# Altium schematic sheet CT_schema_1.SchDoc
size 550 x 503 mm
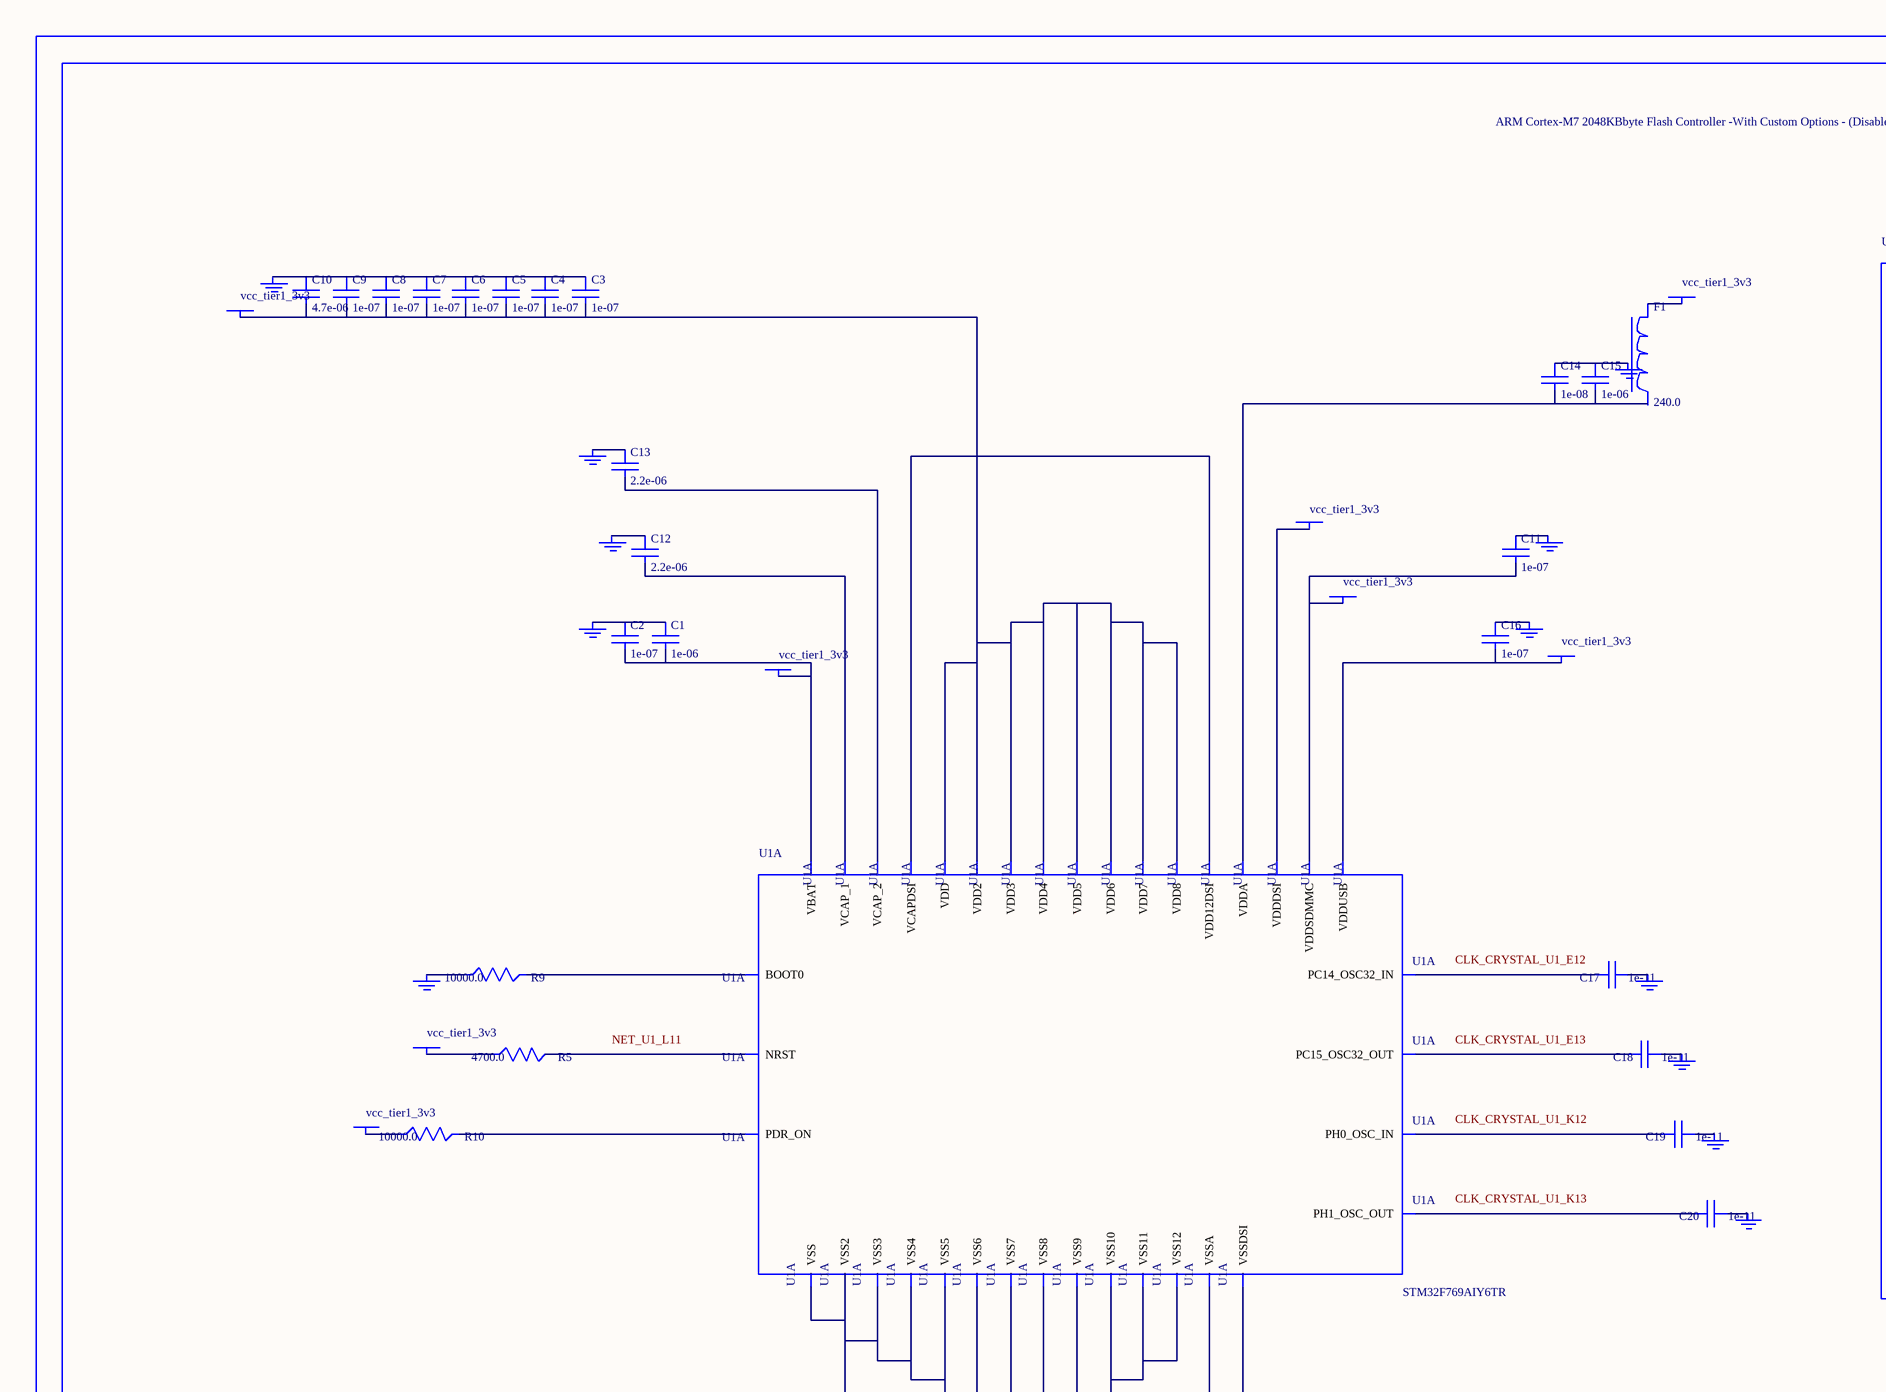
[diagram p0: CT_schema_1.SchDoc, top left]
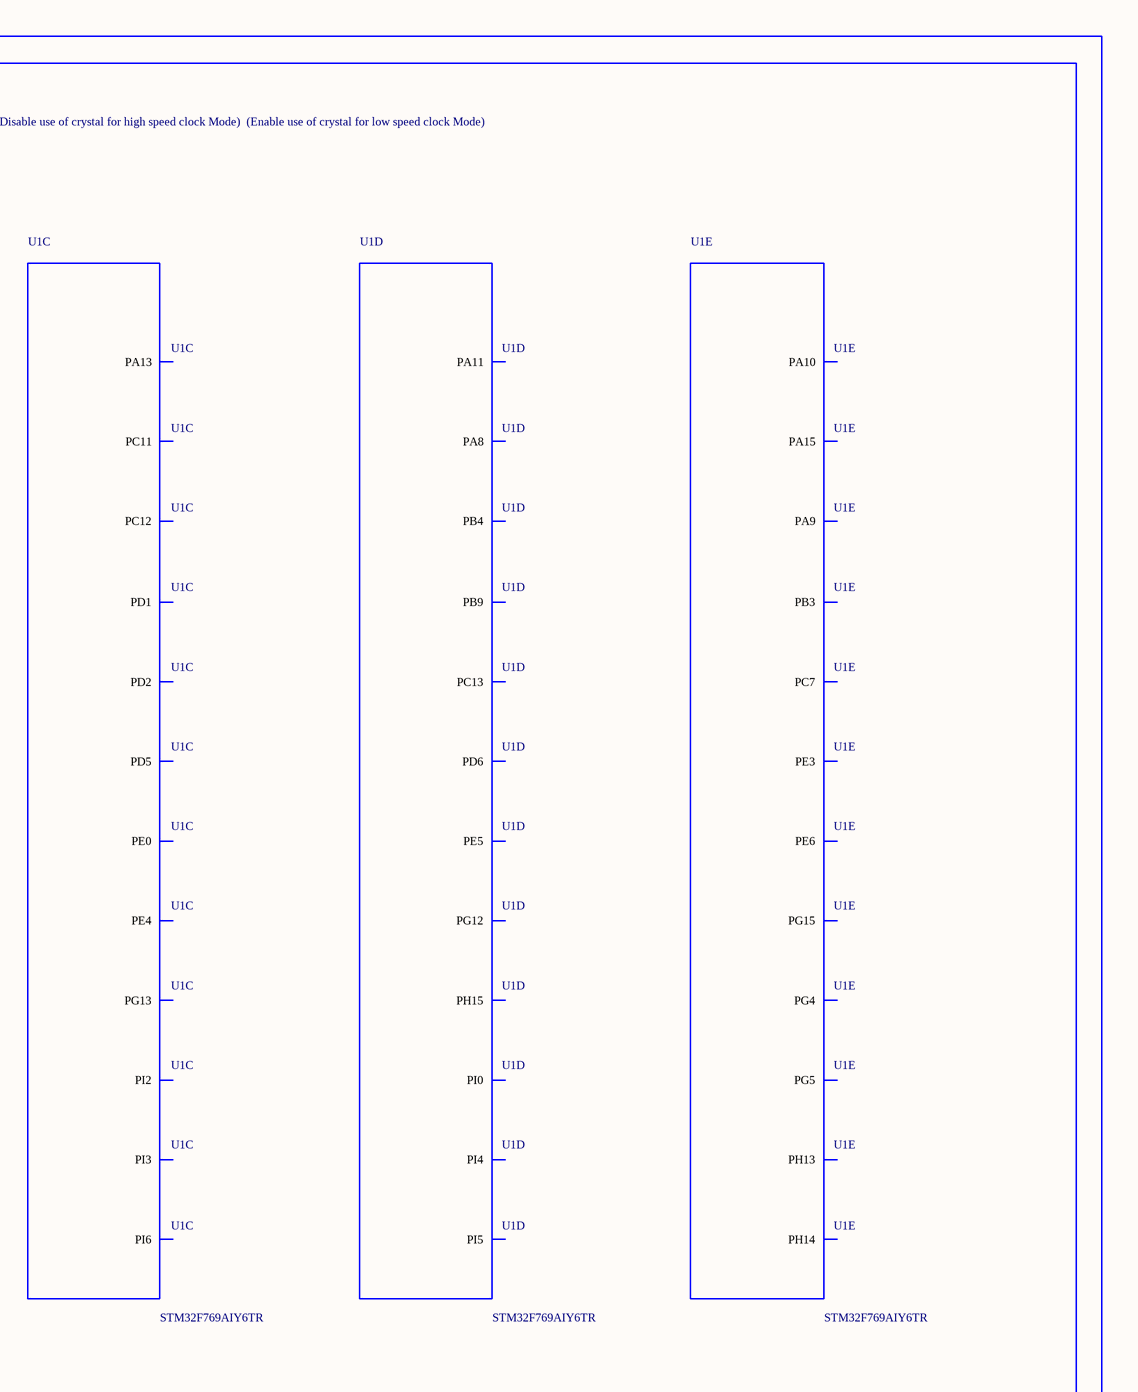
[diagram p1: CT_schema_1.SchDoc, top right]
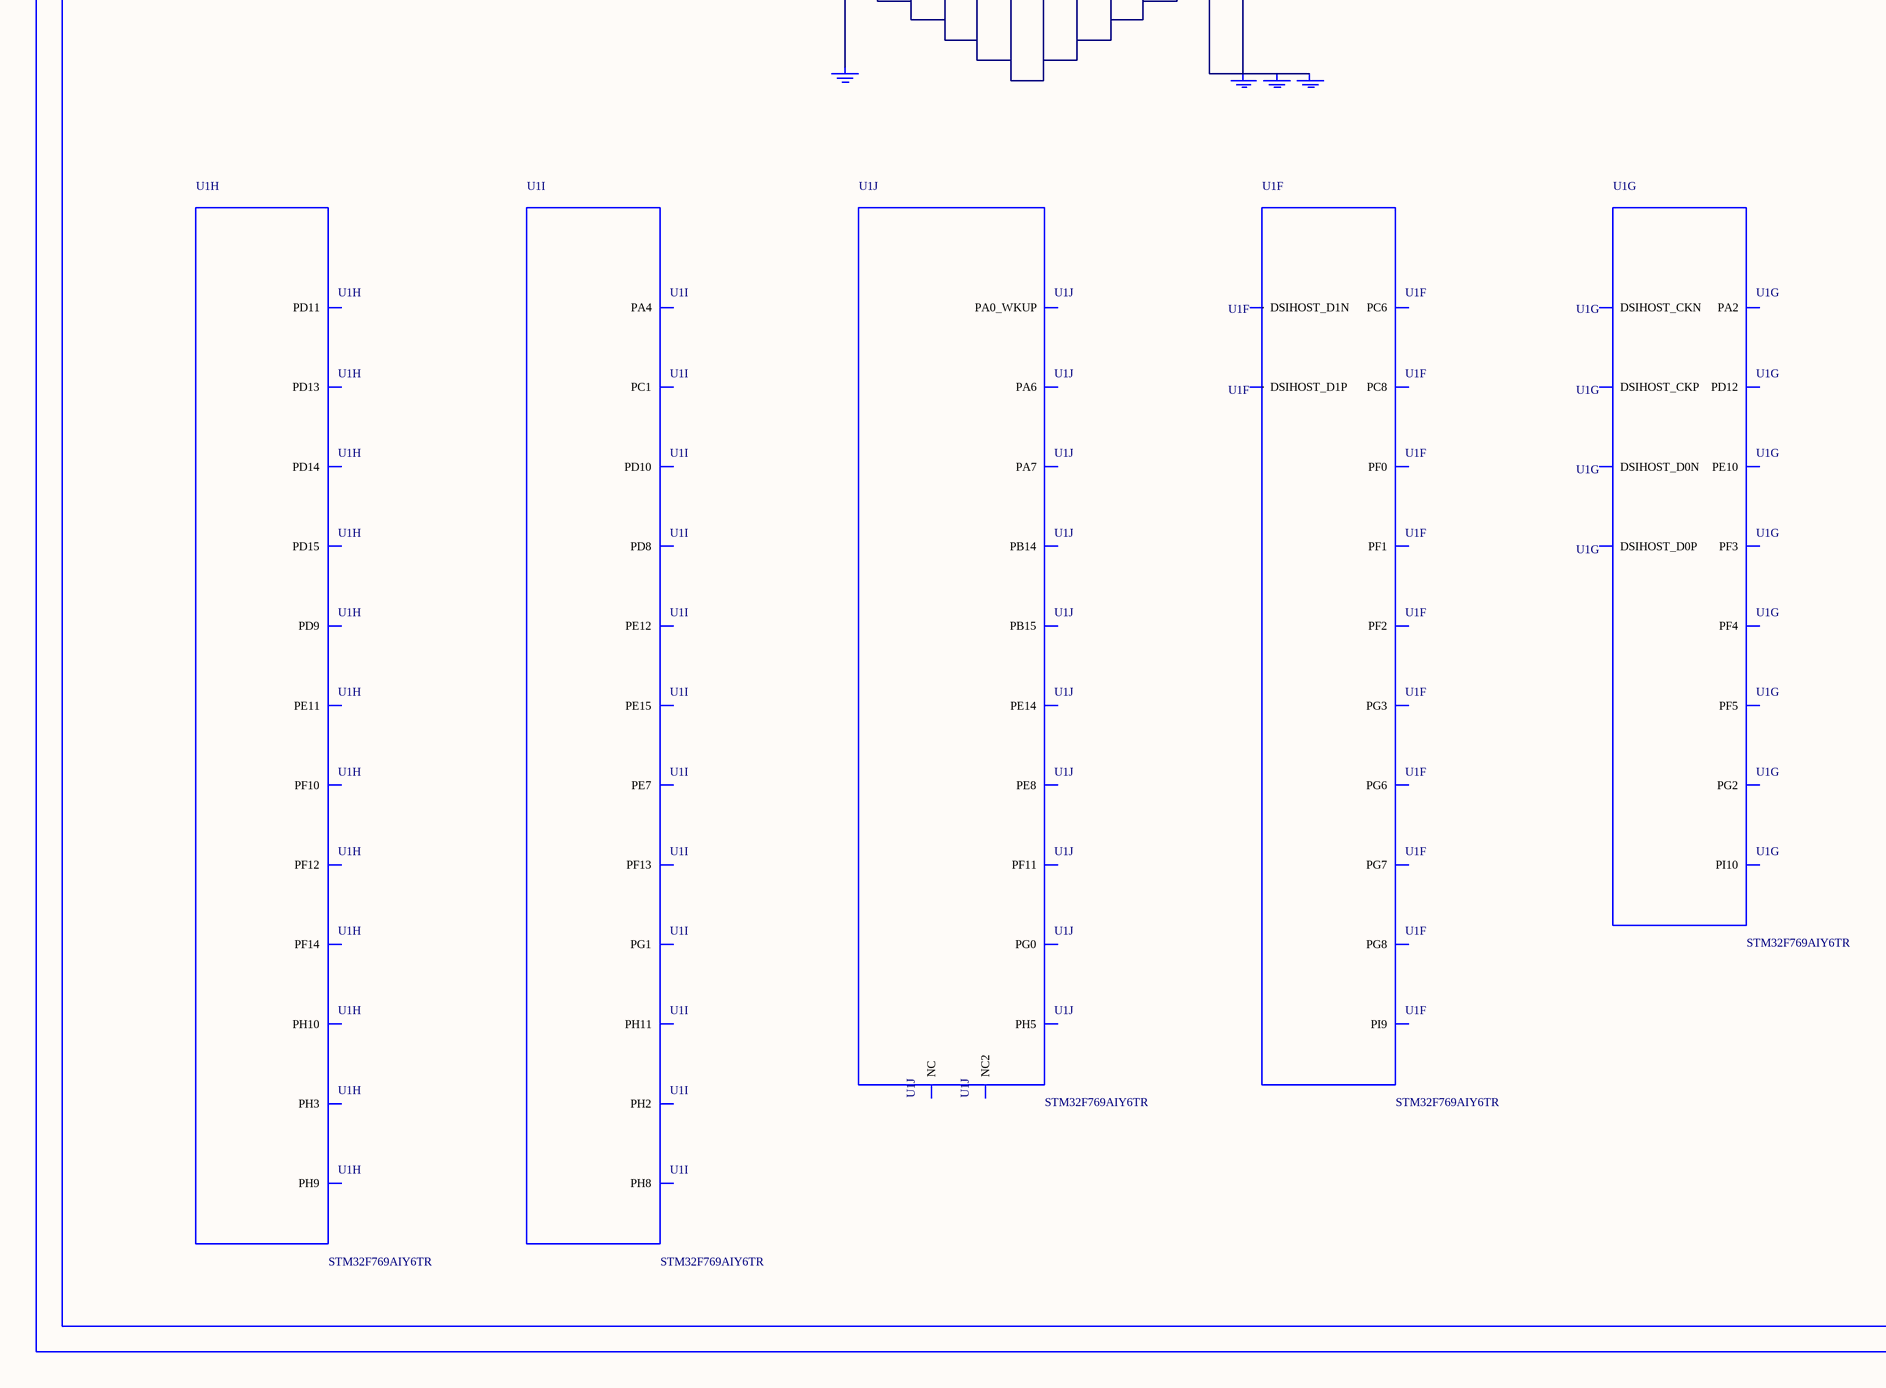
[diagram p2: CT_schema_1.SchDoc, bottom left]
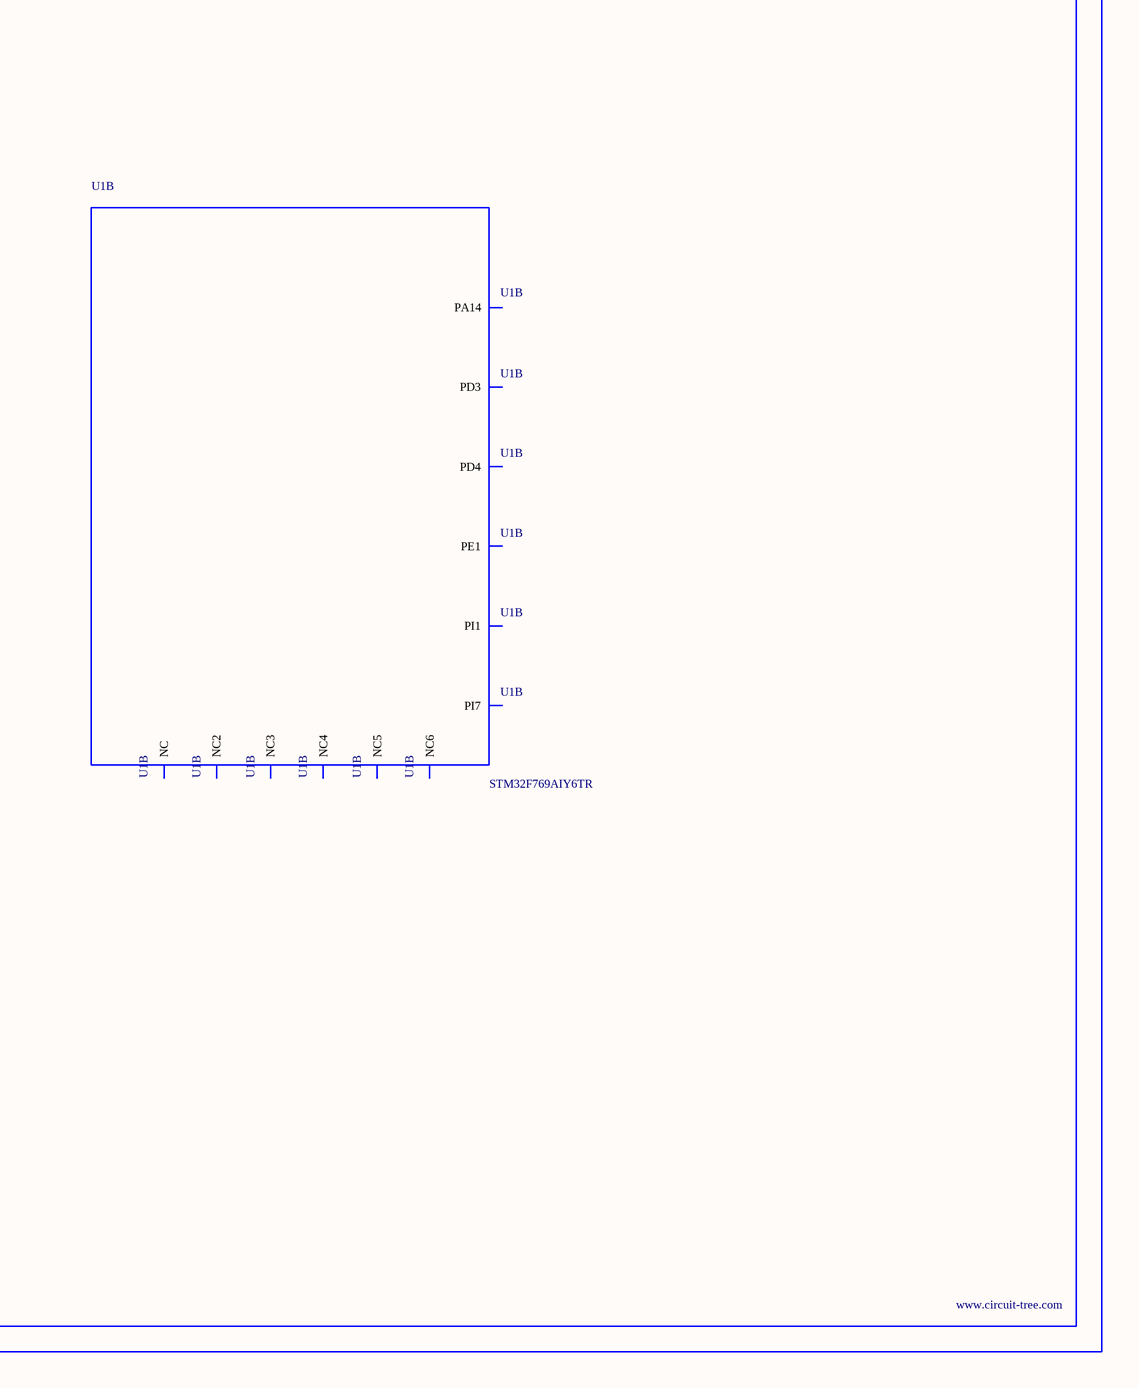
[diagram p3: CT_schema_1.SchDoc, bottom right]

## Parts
BORDER0  (no value)
C1  1e-06  [C0603]
C2  1e-07  [C0603]
C3  1e-07  [C0603]
C4  1e-07  [C0603]
C5  1e-07  [C0603]
C6  1e-07  [C0603]
C7  1e-07  [C0603]
C8  1e-07  [C0603]
C9  1e-07  [C0603]
C10  4.7e-06  [C0603]
C11  1e-07  [C0603]
C12  2.2e-06  [C0603]
C13  2.2e-06  [C0603]
C14  1e-08  [C0603]
C15  1e-06  [C0603]
C16  1e-07  [C0603]
C17  1e-11  [C0402]
C18  1e-11  [C0402]
C19  1e-11  [C0402]
C20  1e-11  [C0402]
F1  240.0  [L0603]
GND_INSTANCE_0_0  (no value)
GND_INSTANCE_0_1  (no value)
GND_INSTANCE_0_2  (no value)
GND_INSTANCE_0_3  (no value)
GND_INSTANCE_0_4  (no value)
GND_INSTANCE_0_5  (no value)
GND_INSTANCE_0_6  (no value)
GND_INSTANCE_0_7  (no value)
GND_INSTANCE_0_8  (no value)
GND_INSTANCE_0_9  (no value)
GND_INSTANCE_0_10  (no value)
GND_INSTANCE_0_11  (no value)
GND_INSTANCE_0_12  (no value)
GND_INSTANCE_0_13  (no value)
GND_INSTANCE_0_14  (no value)
GND_INSTANCE_0_15  (no value)
POWER_INSTANCE_0_0  vcc_tier1_3v3
POWER_INSTANCE_0_1  vcc_tier1_3v3
POWER_INSTANCE_0_2  vcc_tier1_3v3
POWER_INSTANCE_0_3  vcc_tier1_3v3
POWER_INSTANCE_0_4  vcc_tier1_3v3
POWER_INSTANCE_0_5  vcc_tier1_3v3
POWER_INSTANCE_0_6  vcc_tier1_3v3
POWER_INSTANCE_0_7  vcc_tier1_3v3
R5  4700.0  [R0603]
R9  10000.0  [R0603]
R10  10000.0  [R0603]
U1  STM32F769AIY6TR  [WLCSP180]  (parts A,B,C,D,E,F,G,H,I,J of 15)

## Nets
NetC1_1: C1.1 C2.1 GND_INSTANCE_0_0.0(GND)
NetC1_2: C1.2 C2.2 POWER_INSTANCE_0_0.0(PWR) U1.C13(VBAT)
NetC3_1: C3.1 C4.1 C5.1 C6.1 C7.1 C8.1 C9.1 C10.1 GND_INSTANCE_0_2.0(GND)
NetC3_2: C3.2 C4.2 C5.2 C6.2 C7.2 C8.2 C9.2 C10.2 POWER_INSTANCE_0_2.0(PWR) U1.B2(VDD2) U1.B8(VDD3) U1.B11(VDD) U1.F12(VDD4) U1.J12(VDD5) U1.K9(VDD6) U1.M8(VDD7) U1.P4(VDD8)
NetC11_1: C11.1 GND_INSTANCE_0_4.0(GND)
NetC11_2: C11.2 POWER_INSTANCE_0_3.0(PWR) U1.A6(VDDSDMMC)
NetC12_1: C12.1 GND_INSTANCE_0_5.0(GND)
NetC12_2: C12.2 U1.P5(VCAP_1)
NetC13_1: C13.1 GND_INSTANCE_0_6.0(GND)
NetC13_2: C13.2 U1.C1(VCAP_2)
NetC14_1: C14.1 C15.1 GND_INSTANCE_0_1.0(GND)
NetC14_2: C14.2 C15.2 U1.M12(VDDA)
NetC16_1: C16.1 GND_INSTANCE_0_7.0(GND)
NetC16_2: C16.2 POWER_INSTANCE_0_5.0(PWR) U1.F2(VDDUSB)
NetC17_1: C17.1 GND_INSTANCE_0_8.0(GND)
NetC17_2: C17.2 U1.E12(PC14_OSC32_IN)
NetC18_1: C18.1 GND_INSTANCE_0_9.0(GND)
NetC18_2: C18.2 U1.E13(PC15_OSC32_OUT)
NetC19_1: C19.1 GND_INSTANCE_0_10.0(GND)
NetC19_2: C19.2 U1.K12(PH0_OSC_IN)
NetC20_1: C20.1 GND_INSTANCE_0_11.0(GND)
NetC20_2: C20.2 U1.K13(PH1_OSC_OUT)
NetF1_1: F1.1 POWER_INSTANCE_0_1.0(PWR)
NetGND_INSTANCE_0_3_0: GND_INSTANCE_0_3.0(GND) R9.1
NetGND_INSTANCE_0_12_0: GND_INSTANCE_0_12.0(GND) GND_INSTANCE_0_13.0(GND) GND_INSTANCE_0_14.0(GND) U1.H5(VSSDSI) U1.M11(VSSA)
NetGND_INSTANCE_0_15_0: GND_INSTANCE_0_15.0(GND) U1.A8(VSS2) U1.A11(VSS) U1.B6(VSS3) U1.C2(VSS4) U1.F1(VSS5) U1.F13(VSS6) U1.J9(VSS8) U1.J13(VSS7) U1.M1(VSS9) U1.N4(VSS10) U1.N5(VSS11) U1.P9(VSS12)
NetPOWER_INSTANCE_0_4_0: POWER_INSTANCE_0_4.0(PWR) R10.1
NetPOWER_INSTANCE_0_6_0: POWER_INSTANCE_0_6.0(PWR) U1.K1(VDDDSI)
NetPOWER_INSTANCE_0_7_0: POWER_INSTANCE_0_7.0(PWR) R5.1
NetR5_2: R5.2 U1.L11(NRST)
NetR9_2: R9.2 U1.A10(BOOT0)
NetR10_2: R10.2 U1.C10(PDR_ON)
NetU1_H6: U1.H6(VCAPDSI) U1.J3(VDD12DSI)

Not connected (* = marked no-connect by the designer): F1 2; U1 A1(NC) A2(NC4) A3(PA14) A5(PD4) A12(NC2) A13(NC3) B1(NC5) B3(PI1) B5(PD3) B10(PE1) B12(PI7) B13(NC6) C3(PI2) C4(PC11) C5(PD5) C7(PG13) C9(PE0) C11(PI6) C12(PE4) D2(PA13) D3(PI3) D4(PC12) D5(PD1) D6(PD2) D7(PG12) D8(PB4) D9(PB9) D10(PI4) D11(PI5) D12(PE5) D13(PC13) E2(PA8) E3(PA11) E4(PI0) E5(PH15) E6(PD6) E8(PB3) E11(PE6) F3(PC7) F4(PA9) F5(PA10) F6(PH13) F7(PH14) F8(PA15) F9(PG15) F10(PE3) G1(PG4) G2(PG5) G3(PG6) G4(PG7) G5(PG8) G6(PC6) G8(PC8) G9(PG3) G10(PI9) G11(PF0) G12(PF1) G13(PF2) H1(DSIHOST_D1P) H2(DSIHOST_D1N) H3(DSIHOST_CKN) H4(DSIHOST_CKP) H9(PG2) H10(PI10) H11(PF3) H12(PF4) H13(PF5) J1(DSIHOST_D0P) J2(DSIHOST_D0N) J4(PD12) J6(PE10) J10(PA2) K2(PD15) K3(PD11) K4(PH9) K6(PE11) K7(PF12) K8(PF14) K10(PH3) K11(PF10) L1(PD14) L2(PD13) L3(PD9) L4(PH10) L6(PE12) L7(PG1) L8(PF13) L9(PA4) L10(PH2) L13(PC1) M2(PD10) M3(PD8) M4(PH11) M5(PH8) M6(PE15) M7(PE7) M9(PA7) M13(PA0_WKUP) N1(NC) N2(PB15) N3(PB14) N6(PE14) N7(PE8) N8(PG0) N9(PF11) N10(PA6) N11(PH5) N13(NC2)

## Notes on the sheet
- Labels drawn without touching a wire or pin: CLK_CRYSTAL_U1_E12, CLK_CRYSTAL_U1_E13, CLK_CRYSTAL_U1_K12, CLK_CRYSTAL_U1_K13, NET_U1_L11

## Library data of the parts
BORDER0 = BORDER_PAGE0
C1 C15 = C0603C105K3RACTU
C2-C9 C11 C16 = 06035C104K4Z2A
C10 = GRM188R6YA475KE15D
C12 C13 = C0603C225K8RACTU
C14 = 06035C103K4Z2A
C17-C20 = C0402C100K3GACTU
F1 = Z0603C241ASMST
GND_INSTANCE_0_0-GND_INSTANCE_0_15 = GND
POWER_INSTANCE_0_0-POWER_INSTANCE_0_7 = PWR
R5 = RC0603JR-074K7L
R9 R10 = RC0603JR-0710KL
